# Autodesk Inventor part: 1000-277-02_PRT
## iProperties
Created: 2007-03
Part Number: 1000-277-02_PRT
Document SubType Name: Modeling
Designer: Andy Moles
Material: Steel
Mass: 4.57743 g
Surface Area: 6.37278 cm^2
Volume: 0.583113 cm^3
Density: 7.85 g/cm^3
Author: Andy Moles
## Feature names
1. Base1
